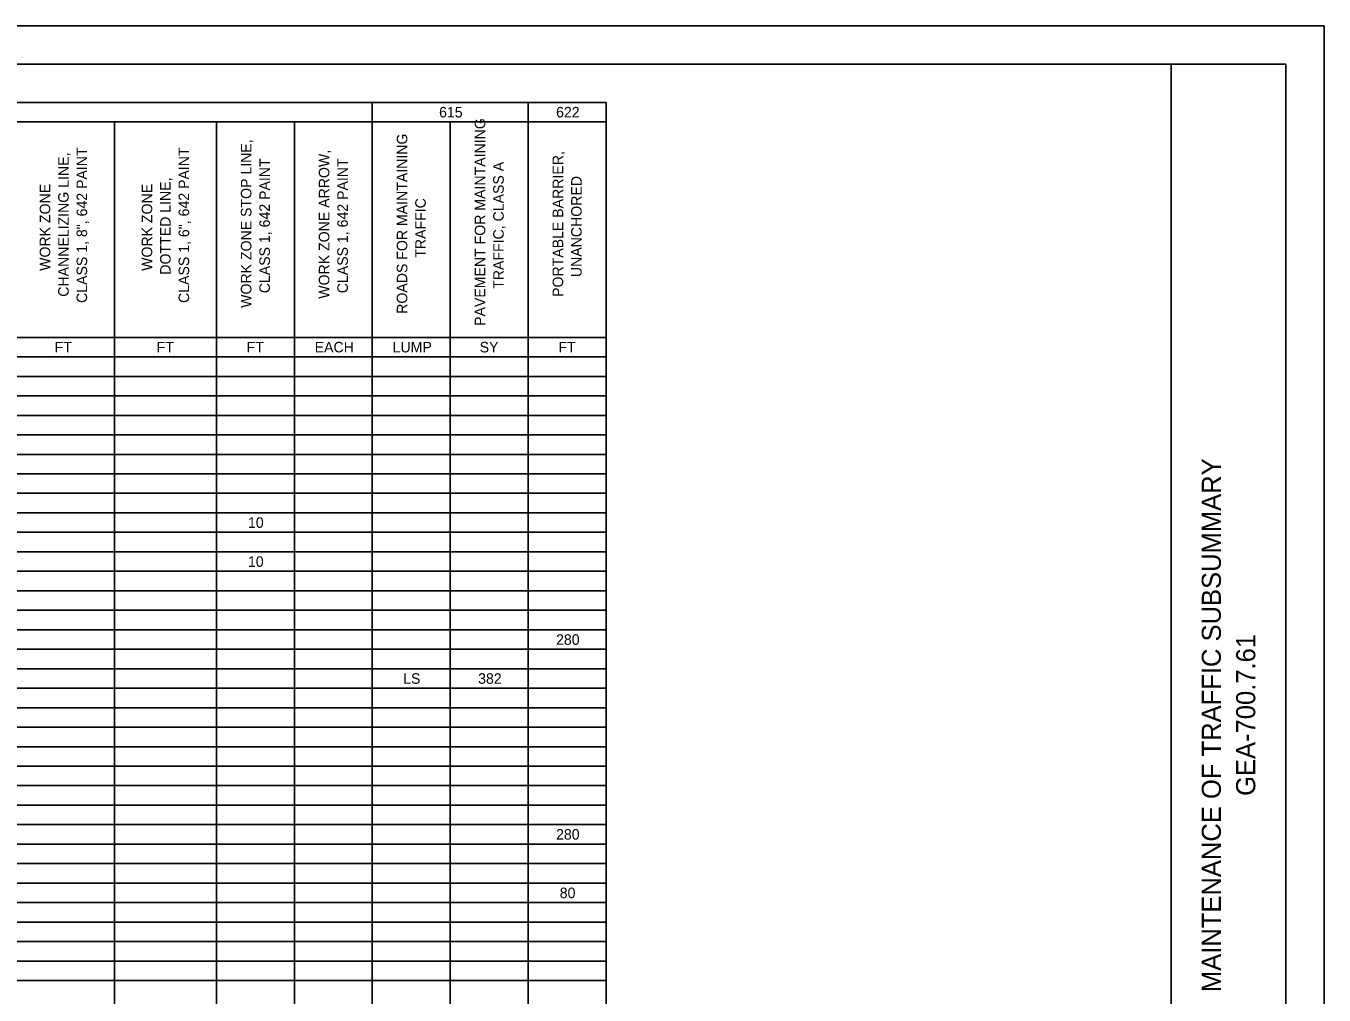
# Model space of a CAD drawing. Extents: x 0 to 34, y 0 to 22.
# Drawn here: x 17.01 to 34, y 9.32 to 22 of the extents above; entities that cross this region are included whole.
import ezdxf

# ---------------------------------------------------------------- set-up
doc = ezdxf.new("R2010")
doc.units = 0
for name, color, linetype in [('SH_Border', 7, 'Continuous'), ('SH_Cut_Line', 7, 'Continuous'), ('SH_Data', 7, 'Continuous'), ('SH_Text', 7, 'Continuous')]:
    doc.layers.add(name, color=color, linetype=linetype)

msp = doc.modelspace()

# ---------------------------------------------------------------- linework, layer by layer
at = {"layer": 'SH_Border'}
msp.add_line((32, 0.5), (32, 21.5), dxfattribs=at)
msp.add_lwpolyline([(1.5, 21.5), (33.5, 21.5), (33.5, 0.5), (1.5, 0.5)], close=True, dxfattribs=at)
at = {"layer": 'SH_Cut_Line'}
msp.add_lwpolyline([(0, 0), (34, 0), (34, 22), (0, 22)], close=True, dxfattribs=at)
at = {"layer": 'SH_Text'}
for p, q in [((2, 21), (24.605, 21)), ((21.545, 21), (21.545, 7.215)), ((23.585, 21), (23.585, 7.215)), ((24.605, 21), (24.605, 7.215)), ((8.045, 20.745), (24.605, 20.745)), ((18.17, 20.745), (18.17, 7.215)), ((19.505, 20.745), (19.505, 7.215)), ((20.525, 20.745), (20.525, 7.215)), ((22.565, 20.745), (22.565, 7.215)), ((8.045, 17.925), (24.605, 17.925)), ((2, 17.67), (24.605, 17.67)), ((2, 17.415), (24.605, 17.415)), ((2, 17.16), (24.605, 17.16)), ((2, 16.905), (24.605, 16.905)), ((2, 16.65), (24.605, 16.65)), ((2, 16.395), (24.605, 16.395)), ((2, 16.14), (24.605, 16.14)), ((2, 15.885), (24.605, 15.885)), ((2, 15.63), (24.605, 15.63)), ((2, 15.375), (24.605, 15.375)), ((2, 15.12), (24.605, 15.12)), ((2, 14.865), (24.605, 14.865)), ((2, 14.61), (24.605, 14.61)), ((2, 14.355), (24.605, 14.355)), ((2, 14.1), (24.605, 14.1)), ((2, 13.845), (24.605, 13.845)), ((2, 13.59), (24.605, 13.59)), ((2, 13.335), (24.605, 13.335)), ((2, 13.08), (24.605, 13.08)), ((2, 12.825), (24.605, 12.825)), ((2, 12.57), (24.605, 12.57)), ((2, 12.315), (24.605, 12.315)), ((2, 12.06), (24.605, 12.06)), ((2, 11.805), (24.605, 11.805)), ((2, 11.55), (24.605, 11.55)), ((2, 11.295), (24.605, 11.295)), ((2, 11.04), (24.605, 11.04)), ((2, 10.785), (24.605, 10.785)), ((2, 10.53), (24.605, 10.53)), ((2, 10.275), (24.605, 10.275)), ((2, 10.02), (24.605, 10.02)), ((2, 9.765), (24.605, 9.765)), ((2, 9.51), (24.605, 9.51))]:
    msp.add_line(p, q, dxfattribs=at)

# ---------------------------------------------------------------- texts
at = {"layer": 'SH_Data'}
for s, p in [('MAINTENANCE OF TRAFFIC SUBSUMMARY', (32.65, 9.359)), ('GEA-700.7.61', (33.1, 11.926))]:
    msp.add_text(s, height=0.25, rotation=90, dxfattribs=at).set_placement(p)
at = {"layer": 'SH_Text'}
for s, p in [('615', (22.419, 20.803)), ('622', (23.95, 20.803)), ('FT', (17.388, 17.729)), ('FT', (18.723, 17.729)), ('FT', (19.9, 17.729)), ('EACH', (20.791, 17.729)), ('LUMP', (21.811, 17.729)), ('SY', (22.95, 17.729)), ('FT', (23.98, 17.729)), ('10', (19.918, 15.433)), ('10', (19.918, 14.923)), ('280', (23.95, 13.903)), ('LS', (21.949, 13.393)), ('382', (22.93, 13.393)), ('280', (23.95, 11.354)), ('80', (23.998, 10.588))]:
    msp.add_text(s, height=0.138, dxfattribs=at).set_placement(p)
for s, p in [('PAVEMENT FOR MAINTAINING ', (23.023, 18.076)), ('ROADS FOR MAINTAINING ', (22.003, 18.234)), ('CLASS 1, 8", 642 PAINT', (17.813, 18.376)), ('CLASS 1, 6", 642 PAINT', (19.148, 18.376)), ('WORK ZONE STOP LINE, ', (19.963, 18.312)), ('CHANNELIZING LINE,', (17.572, 18.457)), ('CLASS 1, 642 PAINT', (20.205, 18.503)), ('WORK ZONE ARROW, ', (20.983, 18.431)), ('CLASS 1, 642 PAINT', (21.225, 18.503)), ('TRAFFIC, CLASS A', (23.265, 18.561)), ('PORTABLE BARRIER, ', (24.043, 18.455)), ('WORK ZONE', (17.33, 18.796)), ('WORK ZONE', (18.665, 18.796)), ('DOTTED LINE,', (18.906, 18.746)), ('UNANCHORED', (24.285, 18.714)), ('TRAFFIC', (22.245, 18.968))]:
    msp.add_text(s, height=0.138, rotation=90, dxfattribs=at).set_placement(p)

doc.saveas('drawing.dxf')
